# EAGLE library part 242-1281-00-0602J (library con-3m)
Zero Insertion Force Socked Source: http://www.3M.com/ehpd
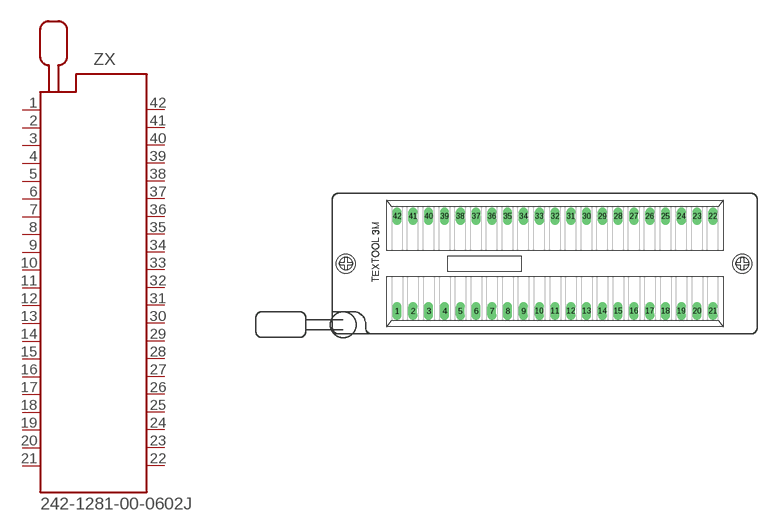
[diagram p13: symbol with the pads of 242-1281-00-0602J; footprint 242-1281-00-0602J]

Designator prefix ZX

## 242-1281-00-0602J (MF: 3M; MPN: 242-1281-00-0602J; OC_FARNELL: unknown; OC_NEWARK: 85K7857)  [242-1281-00-0602J]
1  1  pas
2  2  pas
3  3  pas
4  4  pas
5  5  pas
6  6  pas
7  7  pas
8  8  pas
9  9  pas
10  10  pas
11  11  pas
12  12  pas
13  13  pas
14  14  pas
15  15  pas
16  16  pas
17  17  pas
18  18  pas
19  19  pas
20  20  pas
21  21  pas
22  22  pas
23  23  pas
24  24  pas
25  25  pas
26  26  pas
27  27  pas
28  28  pas
29  29  pas
30  30  pas
31  31  pas
32  32  pas
33  33  pas
34  34  pas
35  35  pas
36  36  pas
37  37  pas
38  38  pas
39  39  pas
40  40  pas
41  41  pas
42  42  pas

## Footprint 242-1281-00-0602J (pad centres in mm)
3M TEXTOOL 42 pol. DIP Lever actuated zero insertion force mechanism Hersteller: 3M TEXTOOL Herstellerbez.: 242-1281-00-0602J Source: http://www.3M.com/ehpd
drill 0.9 long: 1 -25.4,-7.62; 2 -22.86,-7.62; 3 -20.32,-7.62; 4 -17.78,-7.62; 5 -15.24,-7.62; 6 -12.7,-7.62; 7 -10.16,-7.62; 8 -7.62,-7.62; 9 -5.08,-7.62; 10 -2.54,-7.62; 11 0,-7.62; 12 2.54,-7.62; 13 5.08,-7.62; 14 7.62,-7.62; 15 10.16,-7.62; 16 12.7,-7.62; 17 15.24,-7.62; 18 17.78,-7.62; 19 20.32,-7.62; 20 22.86,-7.62; 21 25.4,-7.62; 22 25.4,7.62; 23 22.86,7.62; 24 20.32,7.62; 25 17.78,7.62; 26 15.24,7.62; 27 12.7,7.62; 28 10.16,7.62; 29 7.62,7.62; 30 5.08,7.62; 31 2.54,7.62; 32 0,7.62; 33 -2.54,7.62; 34 -5.08,7.62; 35 -7.62,7.62; 36 -10.16,7.62; 37 -12.7,7.62; 38 -15.24,7.62; 39 -17.78,7.62; 40 -20.32,7.62; 41 -22.86,7.62; 42 -25.4,7.62
hole 2 at 30.13,0
hole 2 at -33.63,0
